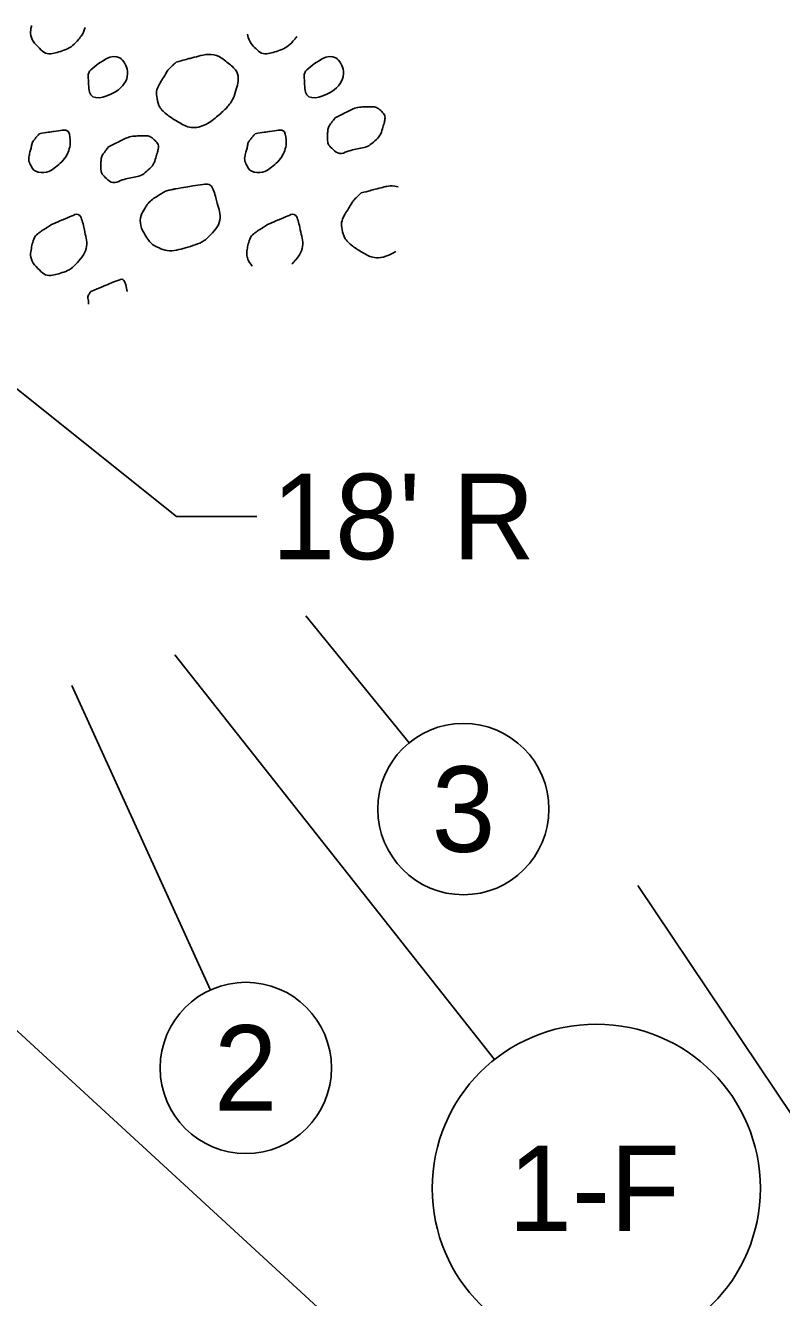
# Model space of a CAD drawing. Extents: x 0 to 3369, y -440 to 440.
# Drawn here: x 417.37 to 442.13, y 244.29 to 285.94 of the extents above; entities that cross this region are included whole.
import ezdxf

# ---------------------------------------------------------------- set-up
doc = ezdxf.new("R2010")
doc.units = 0
doc.layers.add('GE_P_Alignment', color=7, linetype='Continuous')
doc.layers.add('PV_P_EOP', color=7, linetype='Continuous')

msp = doc.modelspace()

# ---------------------------------------------------------------- linework, layer by layer
at = {"layer": 'GE_P_Alignment'}
for points in [[(419.328, 285.871), (419.29, 285.743), (419.222, 285.617), (419.124, 285.499), (418.925, 285.26), (418.697, 285.146), (418.457, 285.074), (418.265, 285.016), (418.024, 285.006), (417.836, 285.192), (417.608, 285.417), (417.523, 285.681), (417.569, 285.91), (417.571, 285.921), (417.573, 285.932), (417.576, 285.943)], [(426.262, 285.586), (426.241, 285.556), (426.219, 285.527), (426.196, 285.499), (425.996, 285.26), (425.769, 285.146), (425.529, 285.074), (425.337, 285.016), (425.095, 285.006), (424.907, 285.192), (424.762, 285.336), (424.675, 285.495), (424.643, 285.652)], [(422.311, 284.745), (422.548, 284.809), (422.785, 284.871), (423.022, 284.932), (423.369, 285.022), (423.717, 284.958), (424.064, 284.669), (424.333, 284.444), (424.35, 284.112), (424.279, 283.864), (424.189, 283.55), (423.991, 283.253), (423.687, 282.994), (423.307, 282.669), (422.779, 282.542), (422.391, 282.772), (422.076, 282.959), (421.743, 283.239), (421.682, 283.569), (421.644, 283.775), (421.751, 284.014), (421.872, 284.205), (421.959, 284.342), (422.035, 284.481), (422.149, 284.59), (422.203, 284.642), (422.256, 284.694), (422.311, 284.745)], [(427.517, 282.917), (427.683, 283.001), (427.85, 283.084), (428.017, 283.167), (428.2, 283.258), (428.419, 283.276), (428.619, 283.282), (428.766, 283.286), (428.908, 283.252), (429.04, 283.12), (429.161, 283), (429.144, 282.84), (429.109, 282.714), (429.05, 282.504), (428.971, 282.29), (428.767, 282.12), (428.567, 281.954), (428.355, 281.93), (428.14, 281.88), (427.915, 281.828), (427.657, 281.694), (427.437, 281.892), (427.291, 282.022), (427.261, 282.175), (427.265, 282.324), (427.269, 282.456), (427.285, 282.613), (427.369, 282.724), (427.418, 282.789), (427.467, 282.853), (427.517, 282.917)], [(417.821, 282.399), (418.075, 282.436), (418.33, 282.477), (418.584, 282.511), (418.811, 282.542), (418.864, 282.051), (418.792, 281.854), (418.713, 281.638), (418.516, 281.422), (418.312, 281.266), (418.103, 281.106), (417.661, 281.132), (417.539, 281.379), (417.462, 281.535), (417.501, 281.715), (417.544, 281.871), (417.574, 281.981), (417.589, 282.107), (417.661, 282.198), (417.714, 282.265), (417.767, 282.332), (417.821, 282.399)], [(424.892, 282.399), (425.147, 282.436), (425.401, 282.477), (425.656, 282.511), (425.883, 282.542), (425.936, 282.051), (425.864, 281.854), (425.785, 281.638), (425.588, 281.422), (425.384, 281.266), (425.174, 281.106), (424.732, 281.132), (424.611, 281.379), (424.534, 281.535), (424.572, 281.715), (424.616, 281.871), (424.646, 281.981), (424.661, 282.107), (424.732, 282.198), (424.786, 282.265), (424.839, 282.332), (424.892, 282.399)], [(420.096, 281.966), (420.262, 282.05), (420.429, 282.133), (420.596, 282.216), (420.779, 282.307), (420.998, 282.325), (421.197, 282.331), (421.344, 282.335), (421.486, 282.301), (421.619, 282.169), (421.74, 282.049), (421.723, 281.889), (421.687, 281.763), (421.628, 281.553), (421.55, 281.339), (421.346, 281.169), (421.146, 281.003), (420.934, 280.979), (420.719, 280.929), (420.494, 280.877), (420.236, 280.743), (420.016, 280.941), (419.87, 281.072), (419.84, 281.224), (419.844, 281.373), (419.847, 281.505), (419.864, 281.662), (419.947, 281.773), (419.997, 281.838), (420.046, 281.902), (420.096, 281.966)], [(422.269, 280.588), (422.572, 280.64), (422.875, 280.697), (423.177, 280.739), (423.48, 280.782), (423.62, 280.263), (423.696, 279.979), (423.764, 279.722), (423.72, 279.407), (423.502, 279.166), (423.236, 278.871), (422.94, 278.758), (422.611, 278.661), (422.328, 278.578), (422.012, 278.548), (421.731, 278.666), (421.56, 278.738), (421.436, 278.862), (421.332, 279.023), (421.159, 279.291), (421.108, 279.66), (421.259, 279.913), (421.359, 280.08), (421.495, 280.229), (421.669, 280.339), (421.816, 280.433), (421.957, 280.521), (422.121, 280.556), (422.176, 280.568), (422.231, 280.579), (422.286, 280.591)], [(429.501, 278.536), (429.159, 278.345), (428.76, 278.301), (428.45, 278.485), (428.134, 278.671), (427.802, 278.951), (427.741, 279.281), (427.703, 279.487), (427.81, 279.726), (427.931, 279.918), (428.017, 280.055), (428.094, 280.193), (428.208, 280.303), (428.262, 280.355), (428.315, 280.407), (428.37, 280.458)], [(428.37, 280.458), (428.607, 280.521), (428.844, 280.583), (429.081, 280.645), (429.247, 280.688), (429.414, 280.695), (429.58, 280.66)], [(418.229, 279.423), (418.463, 279.523), (418.698, 279.624), (418.932, 279.724), (419.175, 279.829), (419.294, 279.295), (419.347, 279.048), (419.404, 278.786), (419.336, 278.492), (419.124, 278.238), (418.925, 277.999), (418.697, 277.885), (418.457, 277.813), (418.265, 277.755), (418.024, 277.745), (417.836, 277.931), (417.608, 278.156), (417.523, 278.421), (417.569, 278.649), (417.605, 278.832), (417.69, 279.071), (417.861, 279.184), (417.983, 279.266), (418.106, 279.343), (418.229, 279.423)], [(425.301, 279.423), (425.535, 279.523), (425.77, 279.624), (426.004, 279.724), (426.247, 279.829), (426.366, 279.295), (426.419, 279.048), (426.476, 278.786), (426.408, 278.492), (426.196, 278.238), (426.162, 278.198), (426.129, 278.162), (426.094, 278.129)], [(424.798, 278.056), (424.653, 278.25), (424.603, 278.462), (424.641, 278.649), (424.677, 278.832), (424.762, 279.071), (424.932, 279.184), (425.055, 279.266), (425.178, 279.343), (425.301, 279.423)], [(419.512, 277.233), (419.829, 277.361), (420.146, 277.497), (420.462, 277.618), (420.604, 277.672), (420.684, 277.39), (420.708, 277.227)], [(419.441, 276.814), (419.439, 276.838), (419.438, 276.863), (419.437, 276.888), (419.434, 276.968), (419.404, 277.057), (419.446, 277.129), (419.467, 277.166), (419.49, 277.198), (419.512, 277.233)]]:
    msp.add_open_spline(points, degree=3, dxfattribs=at)
for points in [[(419.512, 284.494), (420.462, 284.879), (420.714, 284.442), (420.416, 283.837), (419.516, 283.669), (419.437, 284.149), (419.446, 284.39), (419.512, 284.494)], [(426.584, 284.494), (427.534, 284.879), (427.786, 284.442), (427.487, 283.837), (426.587, 283.669), (426.509, 284.149), (426.517, 284.39), (426.584, 284.494)]]:
    msp.add_spline(points, degree=3, dxfattribs=at)
at = {"layer": 'PV_P_EOP'}
for p, q in [((422.318, 269.864), (403.55, 284.861)), ((424.954, 269.864), (422.318, 269.864)), ((429.942, 262.459), (426.559, 266.609)), ((432.735, 252.087), (422.27, 265.335)), ((423.429, 254.362), (418.891, 264.33)), ((432.109, 239.228), (409.302, 260.186)), ((444.926, 246.597), (437.425, 257.786))]:
    msp.add_line(p, q, dxfattribs=at)
for centre, radius in [((431.713, 260.285), 2.804), ((424.591, 251.81), 2.804), ((436.065, 247.871), 5.373)]:
    msp.add_circle(centre, radius, dxfattribs=at)

# ---------------------------------------------------------------- texts
for s, p in [("18' R", (425.431, 268.464)), ('3', (430.676, 258.885)), ('2', (423.545, 250.41)), ('1-F', (433.189, 246.471))]:
    msp.add_text(s, height=2.8, dxfattribs=at).set_placement(p)

doc.saveas('drawing.dxf')
